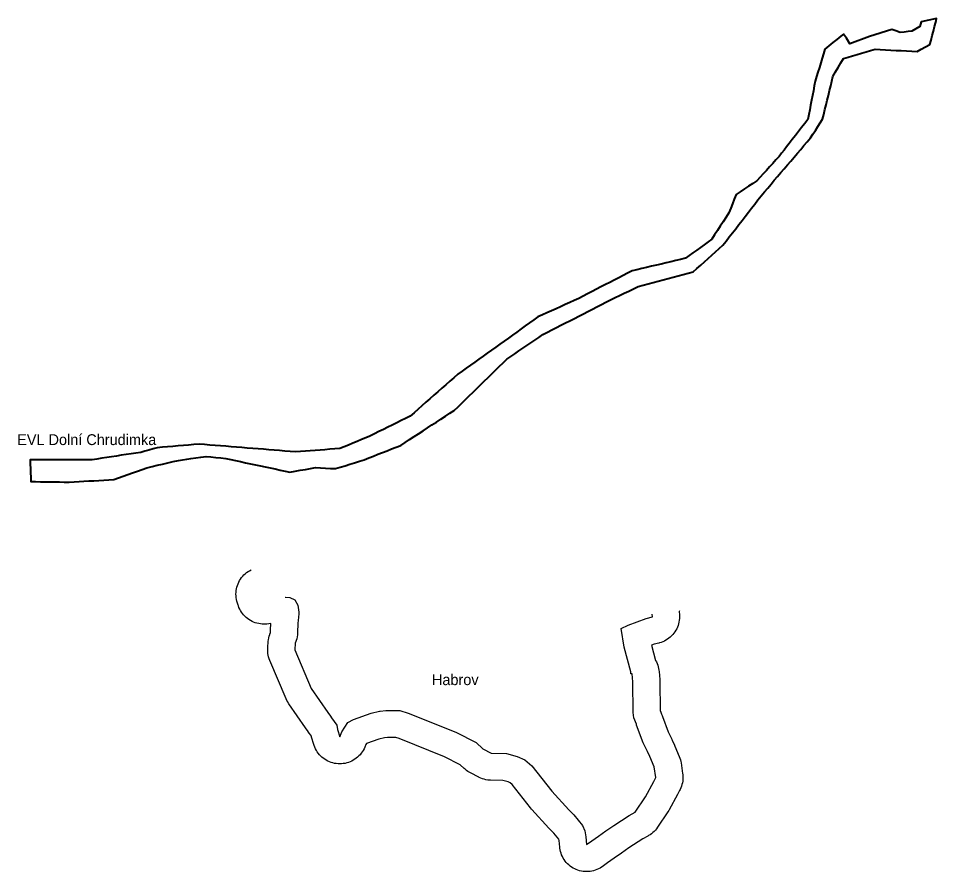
# Model space of a CAD drawing. Extents: x -648743 to -643025, y -1071435 to -1067376.
# Drawn here: x -644723 to -643025, y -1069602 to -1068024 of the extents above; entities that cross this region are included whole.
import ezdxf
from ezdxf.enums import TextEntityAlignment as Align

# ---------------------------------------------------------------- set-up
doc = ezdxf.new("R2010")
doc.units = 0
doc.header["$LTSCALE"] = 4
for name, color, linetype, lineweight in [('22', 7, 'Continuous', 25), ('40', 7, 'Continuous', 40), ('5', 7, 'Continuous', 25)]:
    doc.layers.add(name, color=color, linetype=linetype, lineweight=lineweight)
doc.layers.add('41', color=7, linetype='Continuous')
doc.layers.add('6', color=7, linetype='Continuous')

msp = doc.modelspace()

# ---------------------------------------------------------------- linework, layer by layer
at = {"layer": '22'}
for p, q in [((-643587.875, -1069235.75), (-643590, -1069235.875)), ((-643579.625, -1069330.375), (-643580, -1069329))]:
    msp.add_line(p, q, dxfattribs=at)
for points in [[(-644261.563, -1069191.625), (-644261.456, -1069188.355), (-644261.423, -1069187.882), (-644260.485, -1069175.382), (-644260.197, -1069172.599), (-644259.664, -1069169.37), (-644258.921, -1069166.184), (-644257.971, -1069163.053), (-644257.711, -1069162.306), (-644256.542, -1069159.034), (-644256.426, -1069153.456), (-644256.357, -1069151.674), (-644255.982, -1069145.049), (-644255.968, -1069144.819), (-644255.845, -1069142.799), (-644263.135, -1069143.586), (-644265.23, -1069143.768), (-644268.5, -1069143.875), (-644271.77, -1069143.768), (-644275.026, -1069143.447), (-644278.255, -1069142.914), (-644281.441, -1069142.171), (-644284.572, -1069141.221), (-644287.634, -1069140.069), (-644290.615, -1069138.718), (-644293.5, -1069137.176), (-644296.279, -1069135.448), (-644298.938, -1069133.542), (-644301.467, -1069131.467), (-644303.855, -1069129.23), (-644306.092, -1069126.842), (-644308.168, -1069124.313), (-644310.074, -1069121.653), (-644311.801, -1069118.875), (-644313.344, -1069115.989), (-644314.694, -1069113.009), (-644315.847, -1069109.947), (-644316.243, -1069108.728), (-644317.993, -1069103.103), (-644318.546, -1069101.191), (-644319.289, -1069098.004), (-644319.822, -1069094.776), (-644320.143, -1069091.52), (-644320.25, -1069088.25), (-644320.143, -1069084.98), (-644319.822, -1069081.723), (-644319.289, -1069078.495), (-644318.546, -1069075.309), (-644317.597, -1069072.178), (-644316.444, -1069069.116), (-644315.094, -1069066.135), (-644313.551, -1069063.25), (-644311.824, -1069060.471), (-644309.918, -1069057.812), (-644307.842, -1069055.282), (-644305.605, -1069052.894), (-644303.217, -1069050.658), (-644300.688, -1069048.582), (-644298.029, -1069046.676), (-644295.25, -1069044.949), (-644292.364, -1069043.406), (-644292.262, -1069043.36)], [(-643500.04, -1069119.241), (-643500.999, -1069120.27), (-643500.94, -1069120.897), (-643500.503, -1069125.897), (-643500.42, -1069126.98), (-643500.313, -1069130.25), (-643500.42, -1069133.52), (-643500.741, -1069136.776), (-643501.274, -1069140.004), (-643502.017, -1069143.191), (-643502.967, -1069146.322), (-643504.119, -1069149.384), (-643505.469, -1069152.364), (-643507.012, -1069155.25), (-643508.74, -1069158.028), (-643510.645, -1069160.688), (-643512.721, -1069163.217), (-643514.958, -1069165.605), (-643517.346, -1069167.842), (-643519.875, -1069169.918)], [(-643519.875, -1069169.918), (-643522.535, -1069171.823), (-643525.313, -1069173.551), (-643528.199, -1069175.094), (-643531.179, -1069176.444), (-643534.241, -1069177.596), (-643537.372, -1069178.546), (-643538.547, -1069178.846), (-643547.361, -1069180.98), (-643552.046, -1069182.761), (-643544.492, -1069210.891), (-643543.031, -1069213.635), (-643541.681, -1069216.616), (-643540.528, -1069219.678), (-643539.579, -1069222.809), (-643538.836, -1069225.995), (-643538.303, -1069229.223), (-643538.06, -1069231.455), (-643536.81, -1069245.955), (-643536.732, -1069246.98), (-643536.631, -1069249.486), (-643535.788, -1069304.656), (-643535.753, -1069305.001), (-643533.592, -1069310.391), (-643532.654, -1069312.928), (-643532.045, -1069314.848), (-643521.424, -1069343.062), (-643514.607, -1069356.485), (-643514.344, -1069357.01), (-643513.651, -1069358.476), (-643509.4, -1069367.851), (-643508.743, -1069369.366), (-643508.722, -1069369.417), (-643500.722, -1069388.792), (-643499.59, -1069391.803), (-643498.641, -1069394.934), (-643497.898, -1069398.12), (-643497.488, -1069400.475), (-643494.551, -1069420.1), (-643494.428, -1069420.973), (-643494.107, -1069424.23), (-643494, -1069427.5), (-643494.107, -1069430.77), (-643494.428, -1069434.026), (-643494.961, -1069437.254), (-643495.704, -1069440.441), (-643496.654, -1069443.572), (-643497.806, -1069446.634), (-643499.156, -1069449.614), (-643500.037, -1069451.316), (-643504.082, -1069458.783), (-643519.313, -1069487), (-643520.011, -1069488.25), (-643521.738, -1069491.028), (-643521.809, -1069491.133), (-643540.872, -1069519.508), (-643542.707, -1069522.063), (-643544.783, -1069524.592), (-643547.02, -1069526.98), (-643549.408, -1069529.217), (-643551.937, -1069531.293), (-643554.596, -1069533.198), (-643557.375, -1069534.926), (-643558.743, -1069535.688), (-643568.114, -1069540.714), (-643593.907, -1069557.416), (-643607.546, -1069567.057), (-643621.185, -1069576.729), (-643633.169, -1069585.298), (-643633.437, -1069585.488), (-643643.187, -1069592.363), (-643644.222, -1069593.073), (-643647, -1069594.801), (-643649.886, -1069596.343), (-643652.866, -1069597.694), (-643655.928, -1069598.846), (-643659.059, -1069599.796), (-643662.246, -1069600.539), (-643665.474, -1069601.072), (-643668.73, -1069601.393), (-643672, -1069601.5), (-643675.27, -1069601.393), (-643678.526, -1069601.072), (-643681.755, -1069600.539), (-643684.941, -1069599.796), (-643688.072, -1069598.846), (-643691.134, -1069597.694), (-643694.114, -1069596.343), (-643697, -1069594.801), (-643699.779, -1069593.073), (-643702.438, -1069591.167), (-643704.967, -1069589.092), (-643707.356, -1069586.855), (-643709.592, -1069584.467), (-643711.668, -1069581.938), (-643713.574, -1069579.278), (-643715.301, -1069576.5), (-643716.844, -1069573.614), (-643718.194, -1069570.634), (-643719.347, -1069567.572), (-643720.296, -1069564.441)], [(-643720.296, -1069564.441), (-643721.039, -1069561.254), (-643721.572, -1069558.026), (-643721.752, -1069556.476), (-643723.022, -1069543.773), (-643723.439, -1069541.301), (-643732.461, -1069530.05), (-643739.887, -1069522.817), (-643740.355, -1069522.355), (-643741.673, -1069520.986), (-643773.298, -1069486.861), (-643774.217, -1069485.842), (-643776.028, -1069483.655), (-643809.718, -1069440.528), (-643813.304, -1069437.474), (-643817.369, -1069435.584), (-643827.225, -1069432.981), (-643849.423, -1069432.487), (-643851.582, -1069432.393), (-643854.838, -1069432.072), (-643858.066, -1069431.539), (-643861.253, -1069430.796), (-643864.384, -1069429.846), (-643867.446, -1069428.694), (-643870.426, -1069427.343), (-643871.171, -1069426.969), (-643886.734, -1069418.969), (-643888.875, -1069417.801), (-643891.653, -1069416.073), (-643894.313, -1069414.167), (-643896.842, -1069412.092), (-643898.322, -1069410.741), (-643905.722, -1069403.707), (-643934.497, -1069388.958), (-644018.84, -1069355.435), (-644024.81, -1069353.587), (-644039.874, -1069353.512), (-644045.726, -1069354.069), (-644056.35, -1069356.392), (-644078.825, -1069364.517), (-644080.129, -1069366.499), (-644082.275, -1069371.609), (-644083.531, -1069374.364), (-644085.074, -1069377.25), (-644086.801, -1069380.028), (-644088.707, -1069382.688), (-644090.783, -1069385.217), (-644093.02, -1069387.605), (-644095.408, -1069389.842), (-644097.937, -1069391.918), (-644100.596, -1069393.823), (-644103.375, -1069395.551), (-644106.26, -1069397.093), (-644109.241, -1069398.444), (-644112.303, -1069399.596), (-644115.434, -1069400.546), (-644118.62, -1069401.289), (-644121.849, -1069401.822), (-644125.105, -1069402.143), (-644128.375, -1069402.25), (-644131.645, -1069402.143), (-644134.901, -1069401.822), (-644138.129, -1069401.289), (-644141.316, -1069400.546), (-644144.447, -1069399.596), (-644147.509, -1069398.444), (-644150.489, -1069397.093), (-644153.375, -1069395.551), (-644156.153, -1069393.823), (-644158.813, -1069391.918), (-644161.342, -1069389.842), (-644163.73, -1069387.605), (-644165.967, -1069385.217), (-644168.043, -1069382.688), (-644169.948, -1069380.028), (-644171.676, -1069377.25), (-644173.218, -1069374.364), (-644174.569, -1069371.384), (-644175.721, -1069368.322), (-644176.29, -1069366.538), (-644180.353, -1069352.913), (-644180.734, -1069351.566), (-644180.91, -1069350.892), (-644184.376, -1069345.921), (-644186.548, -1069342.869), (-644186.777, -1069342.545), (-644191.589, -1069335.67), (-644191.722, -1069335.478), (-644222.472, -1069291.103), (-644222.949, -1069290.403), (-644224.676, -1069287.625), (-644226.219, -1069284.739), (-644227.389, -1069282.189), (-644257.577, -1069211.189), (-644257.757, -1069210.759), (-644258.91, -1069207.697), (-644259.859, -1069204.566), (-644260.602, -1069201.379), (-644261.135, -1069198.151), (-644261.456, -1069194.895), (-644261.563, -1069191.625)]]:
    msp.add_lwpolyline(points, dxfattribs=at)
at = {"layer": '40'}
msp.add_line((-643031.02, -1068047.048), (-643028.865, -1068038.737), dxfattribs=at)
for points in [[(-643028.865, -1068038.737), (-643026.71, -1068030.426), (-643024.945, -1068023.617), (-643053.687, -1068030.318), (-643055.952, -1068038.813), (-643063.256, -1068043.074), (-643070.561, -1068047.335), (-643077.866, -1068048.147), (-643085.17, -1068048.958), (-643092.475, -1068049.77), (-643100.562, -1068046.896), (-643107.654, -1068044.376), (-643149.269, -1068057), (-643185.475, -1068070.626), (-643191.79, -1068060.47), (-643197.422, -1068052.611), (-643202.104, -1068056.467), (-643209.43, -1068062.5), (-643216.756, -1068068.534), (-643224.082, -1068074.567), (-643231.408, -1068080.6), (-643233.996, -1068089.066), (-643236.584, -1068097.531), (-643239.172, -1068105.997), (-643241.76, -1068114.463), (-643244.348, -1068122.929), (-643246.936, -1068131.394), (-643249.524, -1068139.86), (-643251.198, -1068148.686), (-643252.872, -1068157.513), (-643254.546, -1068166.339), (-643256.22, -1068175.166), (-643257.893, -1068183.992), (-643259.567, -1068192.818), (-643261.241, -1068201.645), (-643262.915, -1068210.471), (-643268.697, -1068217.914)], [(-643702.982, -1068582.646), (-643694.671, -1068578.337), (-643686.359, -1068574.028), (-643678.048, -1068569.718), (-643669.737, -1068565.409), (-643661.426, -1068561.099), (-643653.115, -1068556.79), (-643644.804, -1068552.48), (-643636.493, -1068548.171), (-643627.996, -1068544.103), (-643619.499, -1068540.036), (-643611.002, -1068535.968), (-643602.504, -1068531.901), (-643594.007, -1068527.833), (-643585.51, -1068523.766), (-643577.013, -1068519.698), (-643567.729, -1068517.194), (-643558.445, -1068514.689), (-643549.161, -1068512.185), (-643539.877, -1068509.68), (-643530.593, -1068507.176), (-643521.309, -1068504.671), (-643512.026, -1068502.167), (-643502.742, -1068499.662), (-643493.458, -1068497.158), (-643484.174, -1068494.653), (-643474.89, -1068492.149), (-643468.024, -1068486.005), (-643461.159, -1068479.862), (-643454.293, -1068473.718), (-643447.427, -1068467.574), (-643440.561, -1068461.431), (-643433.696, -1068455.287), (-643426.83, -1068449.144), (-643419.964, -1068443), (-643414.08, -1068435.391), (-643408.195, -1068427.782), (-643402.311, -1068420.173), (-643396.427, -1068412.564), (-643390.543, -1068404.955), (-643384.658, -1068397.347), (-643378.774, -1068389.738), (-643372.89, -1068382.129), (-643367.006, -1068374.52), (-643361.122, -1068366.911), (-643355.237, -1068359.302), (-643349.353, -1068351.693), (-643343.266, -1068344.551), (-643337.179, -1068337.409), (-643331.092, -1068330.266), (-643325.005, -1068323.124), (-643318.917, -1068315.982), (-643312.83, -1068308.839), (-643306.743, -1068301.697), (-643300.656, -1068294.555), (-643294.569, -1068287.413), (-643288.482, -1068280.27), (-643282.394, -1068273.128), (-643276.307, -1068265.986), (-643270.22, -1068258.843), (-643264.133, -1068251.701), (-643258.046, -1068244.559), (-643253.58, -1068237.624), (-643249.115, -1068230.688), (-643244.649, -1068223.753), (-643240.184, -1068216.817), (-643235.718, -1068209.882), (-643233.589, -1068201.106), (-643231.46, -1068192.329), (-643229.331, -1068183.553), (-643227.202, -1068174.777), (-643225.074, -1068166), (-643222.945, -1068157.224), (-643220.816, -1068148.448), (-643218.687, -1068139.671), (-643216.558, -1068130.895), (-643211.652, -1068122.63), (-643206.745, -1068114.366), (-643201.839, -1068106.102), (-643196.933, -1068097.837), (-643188.622, -1068095.375), (-643180.311, -1068092.912), (-643172, -1068090.45), (-643163.689, -1068087.987), (-643155.378, -1068085.525), (-643147.067, -1068083.062), (-643138.756, -1068080.6), (-643129.06, -1068081.139), (-643119.363, -1068081.677), (-643109.667, -1068082.216), (-643099.971, -1068082.755), (-643090.275, -1068083.293), (-643080.579, -1068083.832), (-643070.882, -1068084.37), (-643061.186, -1068084.909), (-643053.285, -1068080.6), (-643045.385, -1068076.29), (-643037.484, -1068071.981), (-643035.329, -1068063.67), (-643033.175, -1068055.359), (-643031.02, -1068047.048)], [(-643268.697, -1068217.914), (-643274.479, -1068225.357), (-643280.26, -1068232.8), (-643286.042, -1068240.243), (-643291.824, -1068247.686), (-643297.606, -1068255.129), (-643302.241, -1068261.089), (-643306.876, -1068267.048), (-643311.512, -1068273.008), (-643316.147, -1068278.968), (-643322.012, -1068285.401), (-643327.877, -1068291.833), (-643333.742, -1068298.266), (-643339.608, -1068304.698), (-643345.473, -1068311.131), (-643351.338, -1068317.563), (-643357.203, -1068323.996), (-643364.885, -1068329.048), (-643372.568, -1068334.101), (-643380.25, -1068339.153), (-643387.933, -1068344.206), (-643395.615, -1068349.258), (-643398.963, -1068357.78), (-643402.311, -1068366.302), (-643405.659, -1068374.824), (-643409.007, -1068383.346), (-643414.282, -1068391.462), (-643419.558, -1068399.578), (-643424.834, -1068407.694), (-643430.109, -1068415.811), (-643435.384, -1068423.927), (-643440.66, -1068432.043), (-643447.617, -1068437.087), (-643454.574, -1068442.13), (-643461.531, -1068447.174), (-643468.487, -1068452.218), (-643475.444, -1068457.262), (-643482.401, -1068462.305), (-643489.358, -1068467.349), (-643498.323, -1068469.452), (-643507.288, -1068471.555), (-643516.252, -1068473.657), (-643525.217, -1068475.76), (-643534.182, -1068477.863), (-643543.146, -1068479.966), (-643552.111, -1068482.069), (-643561.076, -1068484.172), (-643570.041, -1068486.274), (-643579.005, -1068488.377), (-643587.97, -1068490.48), (-643596.188, -1068494.741), (-643604.405, -1068499.002), (-643612.623, -1068503.263), (-643620.841, -1068507.524), (-643629.058, -1068511.785), (-643637.276, -1068516.046), (-643645.494, -1068520.307), (-643653.711, -1068524.568), (-643661.929, -1068528.829), (-643670.147, -1068533.09), (-643678.364, -1068537.351), (-643686.582, -1068541.612), (-643694.969, -1068545.4), (-643703.355, -1068549.187), (-643711.742, -1068552.975), (-643720.129, -1068556.762), (-643728.515, -1068560.55), (-643736.902, -1068564.337), (-643745.289, -1068568.125), (-643753.675, -1068571.912), (-643762.062, -1068575.7), (-643769.856, -1068581.282), (-643777.649, -1068586.865), (-643785.443, -1068592.447), (-643793.236, -1068598.029), (-643801.03, -1068603.611), (-643808.824, -1068609.194), (-643816.617, -1068614.776), (-643824.411, -1068620.358), (-643832.205, -1068625.94), (-643839.998, -1068631.523), (-643847.792, -1068637.105), (-643855.586, -1068642.687), (-643863.379, -1068648.269), (-643871.173, -1068653.852), (-643878.966, -1068659.434), (-643886.76, -1068665.016), (-643894.554, -1068670.599), (-643902.347, -1068676.181), (-643910.141, -1068681.763), (-643917.503, -1068688.227), (-643924.865, -1068694.691), (-643932.227, -1068701.155), (-643939.589, -1068707.62), (-643946.951, -1068714.084), (-643954.312, -1068720.548), (-643961.674, -1068727.012), (-643969.036, -1068733.476), (-643976.398, -1068739.94), (-643983.76, -1068746.405), (-643991.122, -1068752.869)], [(-644546.088, -1068876.406), (-644537.392, -1068873.275), (-644528.696, -1068870.145), (-644520, -1068867.014), (-644511.305, -1068863.884), (-644502.609, -1068860.753), (-644493.913, -1068857.623), (-644485.217, -1068854.492), (-644475.477, -1068852.26), (-644465.738, -1068850.028), (-644455.999, -1068847.796), (-644446.259, -1068845.564), (-644436.519, -1068843.332), (-644426.78, -1068841.1), (-644419.07, -1068839.883), (-644411.359, -1068838.665), (-644403.649, -1068837.448), (-644394.315, -1068836.231), (-644384.982, -1068835.013), (-644375.648, -1068833.796), (-644366.517, -1068834.709), (-644357.387, -1068835.622), (-644348.256, -1068836.535), (-644339.125, -1068837.448), (-644329.994, -1068839.395), (-644320.862, -1068841.342), (-644311.731, -1068843.289), (-644302.6, -1068845.236), (-644293.469, -1068847.183), (-644284.338, -1068849.13), (-644275.206, -1068851.077), (-644266.075, -1068853.024), (-644256.944, -1068854.971), (-644247.813, -1068856.918), (-644238.681, -1068858.865), (-644229.55, -1068860.812), (-644220.419, -1068862.759), (-644210.938, -1068861.035), (-644201.458, -1068859.311), (-644191.977, -1068857.588), (-644182.497, -1068855.864), (-644173.016, -1068854.14), (-644163.858, -1068854.679), (-644154.701, -1068855.218), (-644145.543, -1068855.756), (-644136.386, -1068856.295), (-644127.505, -1068853.536), (-644118.623, -1068850.778), (-644109.742, -1068848.019), (-644100.86, -1068845.26), (-644091.978, -1068842.502), (-644083.097, -1068839.743), (-644074.675, -1068836.425), (-644066.253, -1068833.107), (-644057.831, -1068829.789), (-644049.41, -1068826.472), (-644040.988, -1068823.154), (-644032.566, -1068819.836), (-644024.144, -1068816.518), (-644015.722, -1068813.2), (-644007.462, -1068807.813), (-643999.203, -1068802.426), (-643990.943, -1068797.04), (-643982.683, -1068791.653), (-643974.424, -1068786.266), (-643966.164, -1068780.88), (-643957.904, -1068775.493), (-643949.645, -1068770.106), (-643941.385, -1068764.719), (-643933.125, -1068759.333), (-643924.866, -1068753.946), (-643916.606, -1068748.559), (-643909.68, -1068741.787), (-643902.754, -1068735.015), (-643895.828, -1068728.243), (-643888.903, -1068721.471), (-643881.977, -1068714.699), (-643875.051, -1068707.927), (-643868.125, -1068701.155), (-643861.199, -1068694.384), (-643854.273, -1068687.612), (-643847.347, -1068680.84), (-643840.422, -1068674.068), (-643833.496, -1068667.296), (-643826.57, -1068660.524), (-643819.644, -1068653.752), (-643812.222, -1068648.724), (-643804.8, -1068643.697), (-643797.379, -1068638.669), (-643789.957, -1068633.641), (-643782.535, -1068628.614), (-643775.113, -1068623.586), (-643767.692, -1068618.558), (-643760.27, -1068613.531), (-643752.848, -1068608.503), (-643744.537, -1068604.194), (-643736.226, -1068599.884), (-643727.915, -1068595.575), (-643719.604, -1068591.265), (-643711.293, -1068586.956), (-643702.982, -1068582.646)], [(-643991.122, -1068752.869), (-643998.484, -1068759.333), (-644006.709, -1068763.413), (-644014.934, -1068767.493), (-644023.158, -1068771.574), (-644031.383, -1068775.654), (-644039.608, -1068779.734), (-644047.833, -1068783.814), (-644056.057, -1068787.895), (-644064.282, -1068791.975), (-644072.507, -1068796.055), (-644080.507, -1068799.359), (-644088.508, -1068802.664), (-644096.508, -1068805.968), (-644104.508, -1068809.273), (-644112.508, -1068812.577), (-644120.509, -1068815.882), (-644128.509, -1068819.186), (-644137.572, -1068819.862), (-644146.635, -1068820.539), (-644155.698, -1068821.215), (-644164.761, -1068821.892), (-644173.825, -1068822.568), (-644182.888, -1068823.245), (-644191.951, -1068823.921), (-644201.014, -1068824.598), (-644210.077, -1068825.274), (-644219.989, -1068824.484), (-644229.9, -1068823.693), (-644239.812, -1068822.903), (-644249.724, -1068822.112), (-644259.635, -1068821.322), (-644269.547, -1068820.531), (-644279.459, -1068819.741), (-644289.37, -1068818.95), (-644299.282, -1068818.16), (-644309.194, -1068817.37), (-644319.105, -1068816.579), (-644329.017, -1068815.789), (-644338.929, -1068814.998), (-644348.84, -1068814.208), (-644358.752, -1068813.417), (-644368.664, -1068812.627), (-644378.575, -1068811.836), (-644388.487, -1068811.046), (-644398.183, -1068811.854), (-644407.879, -1068812.662), (-644417.575, -1068813.47), (-644427.272, -1068814.278), (-644436.968, -1068815.086), (-644446.664, -1068815.894), (-644456.36, -1068816.702), (-644466.056, -1068817.51), (-644473.597, -1068819.665), (-644481.139, -1068821.819), (-644488.681, -1068823.974), (-644496.222, -1068826.129), (-644505.226, -1068827.504), (-644514.23, -1068828.88), (-644523.235, -1068830.255), (-644532.239, -1068831.631), (-644541.243, -1068833.006), (-644550.247, -1068834.381), (-644559.251, -1068835.757), (-644568.256, -1068837.132), (-644577.26, -1068838.508), (-644586.264, -1068839.883), (-644595.802, -1068839.88), (-644605.34, -1068839.876), (-644614.877, -1068839.873), (-644624.415, -1068839.869), (-644633.953, -1068839.866), (-644643.491, -1068839.863), (-644653.029, -1068839.859), (-644662.567, -1068839.856), (-644672.105, -1068839.852), (-644681.642, -1068839.849), (-644691.18, -1068839.845), (-644700.718, -1068839.842), (-644700.471, -1068847.885), (-644700.225, -1068855.928), (-644699.978, -1068863.972), (-644699.732, -1068872.015), (-644699.485, -1068880.058), (-644690.659, -1068880.21), (-644681.832, -1068880.363), (-644673.006, -1068880.515), (-644664.179, -1068880.667), (-644655.353, -1068880.819), (-644646.527, -1068880.972), (-644637.7, -1068881.124), (-644628.874, -1068881.276), (-644619.676, -1068880.735), (-644610.477, -1068880.194), (-644601.279, -1068879.653), (-644592.08, -1068879.112), (-644582.882, -1068878.57), (-644573.683, -1068878.029), (-644564.485, -1068877.488), (-644555.286, -1068876.947), (-644546.088, -1068876.406)]]:
    msp.add_lwpolyline(points, dxfattribs=at)
at = {"layer": '5'}
for points in [[(-644229.07, -1069093.819), (-644229, -1069093.875), (-644221, -1069094.5), (-644211.688, -1069098.75), (-644205.938, -1069108.625)], [(-644205.938, -1069108.625), (-644203.937, -1069121.625), (-644204, -1069124.875), (-644205.125, -1069137.375)], [(-644205.125, -1069137.375), (-644205.687, -1069141.75), (-644206.062, -1069147.875), (-644206.437, -1069154.5), (-644206.625, -1069163.5), (-644207.812, -1069171.25), (-644210.625, -1069179.125), (-644211.563, -1069191.625)], [(-643602.813, -1069186.5), (-643608.312, -1069151.875), (-643595.062, -1069145.625), (-643562.187, -1069133.125), (-643550.313, -1069130.25)], [(-643550.313, -1069130.25), (-643550.75, -1069125.25), (-643550.753, -1069125.237)], [(-643587.875, -1069235.75), (-643590, -1069235.875), (-643590.562, -1069232.125), (-643602.813, -1069186.5)], [(-644211.563, -1069191.625), (-644181.375, -1069262.625), (-644150.625, -1069307), (-644145.813, -1069313.875), (-644143.5, -1069317.125)], [(-643567.25, -1069363.25), (-643579.625, -1069330.375), (-643580, -1069329), (-643584.812, -1069317), (-643585.75, -1069307.5), (-643586.625, -1069250.25), (-643587.875, -1069235.75)], [(-644128.375, -1069352.25), (-644124.438, -1069342.875), (-644113.25, -1069325.875), (-644102.75, -1069320), (-644070.25, -1069308.25)], [(-644070.25, -1069308.25), (-644054.813, -1069304.875), (-644053.938, -1069304.625), (-644043.428, -1069303.624), (-644042.125, -1069303.5), (-644017.125, -1069303.625)], [(-644017.125, -1069303.625), (-644002.187, -1069308.25), (-643913.813, -1069343.375), (-643876.5, -1069362.5), (-643863.875, -1069374.5), (-643848.312, -1069382.5), (-643820.188, -1069383.125)], [(-644143.5, -1069317.125), (-644134, -1069330.75), (-644132.438, -1069338.625), (-644128.375, -1069352.25)], [(-643546.937, -1069407.875), (-643554.937, -1069388.5), (-643559.188, -1069379.125), (-643567.25, -1069363.25)], [(-643820.188, -1069383.125), (-643800.312, -1069388.375), (-643786.062, -1069395)], [(-643786.062, -1069395), (-643773.438, -1069405.75), (-643736.625, -1069452.875)], [(-643582.375, -1069491.625), (-643563.312, -1069463.25), (-643548.063, -1069435), (-643544, -1069427.5), (-643546.937, -1069407.875)], [(-643736.625, -1069452.875), (-643705, -1069487), (-643695.375, -1069496.375), (-643679.437, -1069516.25), (-643675.312, -1069526), (-643673.438, -1069537.125)], [(-643636.438, -1069526.25), (-643621.938, -1069516), (-643593.562, -1069497.625), (-643582.375, -1069491.625)], [(-643673.438, -1069537.125), (-643672, -1069551.5), (-643662.25, -1069544.625), (-643650.187, -1069536), (-643636.438, -1069526.25)]]:
    msp.add_lwpolyline(points, dxfattribs=at)

# ---------------------------------------------------------------- texts
at = {"layer": '41'}
msp.add_text('EVL Dolní Chrudimka', height=20, dxfattribs=at).set_placement((-644596.199, -1068812.692), align=Align.CENTER)
at = {"layer": '6'}
msp.add_text('Habrov', height=20, dxfattribs=at).set_placement((-643914.863, -1069256.576), align=Align.CENTER)

doc.saveas('drawing.dxf')
